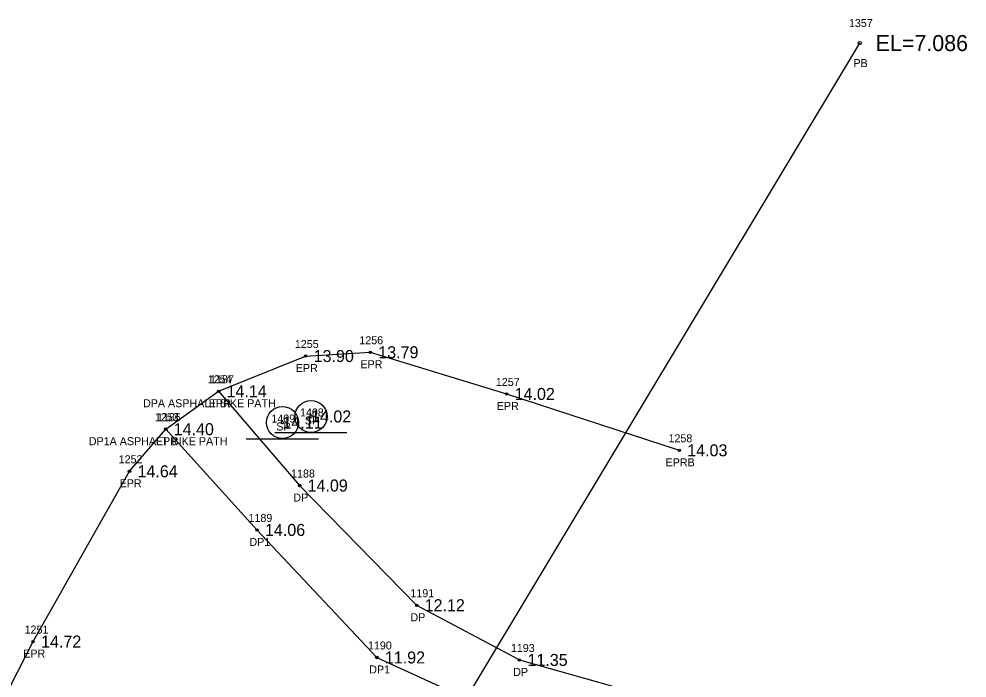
# Model space of a CAD drawing. Extents: x 2072307 to 2072993, y 127574 to 129736.
# Drawn here: x 2072874.9 to 2072993.3, y 128591.5 to 128673.9 of the extents above; entities that cross this region are included whole.
import ezdxf

# ---------------------------------------------------------------- set-up
doc = ezdxf.new("R2010")
doc.units = 0
for name, color, linetype in [('RD_EX_BldgApp', 7, 'Continuous'), ('RD_EX_BldgApp_txCode', 7, 'Continuous'), ('RD_EX_DR_Pipe', 7, 'Continuous'), ('RD_EX_DR_Pipe_txCode', 7, 'Continuous'), ('RD_EX_Driveway', 7, 'Continuous'), ('RD_EX_Driveway_txCode', 7, 'Continuous'), ('RD_EX_Road', 7, 'Continuous'), ('RD_EX_Road_txCode', 7, 'Continuous'), ('RD_EX_TX_BldgApp_ELEV', 7, 'Continuous'), ('RD_EX_TX_Driveway_ELEV', 7, 'Continuous'), ('RD_EX_TX_Road_ELEV', 7, 'Continuous'), ('RD_SMD_Locator', 7, 'Continuous'), ('RD_TX_Pipe_ElevEX', 7, 'Continuous')]:
    doc.layers.add(name, color=color, linetype=linetype)

msp = doc.modelspace()

# ---------------------------------------------------------------- linework, layer by layer
at = {"layer": 'RD_EX_BldgApp'}
for p, q in [((2072906.88, 128622.19), (2072915.88, 128622.19)), ((2072903.31, 128621.42), (2072912.31, 128621.42))]:
    msp.add_line(p, q, dxfattribs=at)
for centre in [(2072907.82, 128623.45), (2072911.39, 128624.21)]:
    msp.add_circle(centre, 2, dxfattribs=at)
at = {"layer": 'RD_EX_DR_Pipe'}
msp.add_line((2072924.18, 128577.97), (2072979.91, 128670.87), dxfattribs=at)
at = {"layer": 'RD_EX_Driveway'}
for points in [[(2072899.84, 128627.36), (2072909.96, 128615.58), (2072924.58, 128600.62), (2072937.42, 128593.78), (2072957.44, 128588.15)], [(2072893.24, 128622.62), (2072904.64, 128610.03), (2072919.61, 128594.09), (2072934.96, 128587.05), (2072955.54, 128580.39)]]:
    msp.add_lwpolyline(points, dxfattribs=at)
at = {"layer": 'RD_EX_Road'}
msp.add_lwpolyline([(2072789.45, 128345.69), (2072789.46, 128382.93), (2072788.01, 128408.09), (2072794.06, 128431.26), (2072804.3, 128453.88), (2072840.7, 128525.64), (2072876.68, 128596.08), (2072888.72, 128617.36), (2072893.24, 128622.62), (2072899.84, 128627.36), (2072910.72, 128631.76), (2072918.79, 128632.23), (2072935.82, 128627.02), (2072957.37, 128619.98)], dxfattribs=at)
at = {"layer": 'RD_SMD_Locator'}
for centre, radius in [((2072979.91, 128670.87), 0.2), ((2072910.72, 128631.76), 0.15), ((2072918.79, 128632.23), 0.15), ((2072899.84, 128627.36), 0.15), ((2072899.84, 128627.36), 0.15), ((2072935.82, 128627.02), 0.15), ((2072911.39, 128624.21), 0.15), ((2072907.82, 128623.45), 0.15), ((2072893.24, 128622.62), 0.15), ((2072893.24, 128622.62), 0.15), ((2072957.37, 128619.98), 0.15), ((2072888.72, 128617.36), 0.15), ((2072909.96, 128615.58), 0.15), ((2072904.64, 128610.03), 0.15), ((2072924.58, 128600.62), 0.15), ((2072876.68, 128596.08), 0.15), ((2072919.61, 128594.09), 0.15), ((2072937.42, 128593.78), 0.15)]:
    msp.add_circle(centre, radius, dxfattribs=at)

# ---------------------------------------------------------------- texts
at = {"layer": 'RD_EX_BldgApp_txCode'}
for s, p in [('1409', (2072906.44, 128623.45)), ('1408', (2072910.01, 128624.21)), ('SP', (2072910.62, 128623.21)), ('SP', (2072907.05, 128622.45))]:
    msp.add_text(s, height=1, dxfattribs=at).set_placement(p)
at = {"layer": 'RD_EX_DR_Pipe_txCode'}
for s, p in [('1357', (2072978.56, 128672.87)), ('PB', (2072979.13, 128667.87))]:
    msp.add_text(s, height=1, dxfattribs=at).set_placement(p)
at = {"layer": 'RD_EX_Driveway_txCode'}
for s, p in [('1187', (2072898.78, 128628.36)), ('DPA ASPHALT BIKE PATH', (2072890.41, 128625.36)), ('1186', (2072892.15, 128623.62)), ('DP1A ASPHALT BIKE PATH', (2072883.64, 128620.62)), ('1188', (2072908.9, 128616.58)), ('DP', (2072909.18, 128613.58)), ('1189', (2072903.58, 128611.03)), ('DP1', (2072903.7, 128608.03)), ('1191', (2072923.8, 128601.62)), ('DP', (2072923.8, 128598.62)), ('1190', (2072918.5, 128595.09)), ('1193', (2072936.35, 128594.78)), ('DP1', (2072918.66, 128592.09)), ('DP', (2072936.64, 128591.78))]:
    msp.add_text(s, height=1, dxfattribs=at).set_placement(p)
at = {"layer": 'RD_EX_Road_txCode'}
for s, p in [('1255', (2072909.37, 128632.76)), ('1256', (2072917.42, 128633.23)), ('EPR', (2072909.49, 128629.76)), ('EPR', (2072917.56, 128630.23)), ('1254', (2072898.5, 128628.36)), ('1257', (2072934.47, 128628.02)), ('EPR', (2072898.61, 128625.36)), ('EPR', (2072934.59, 128625.02)), ('1253', (2072891.89, 128623.62)), ('1258', (2072956.03, 128620.98)), ('EPR', (2072892.01, 128620.62)), ('1252', (2072887.37, 128618.36)), ('EPRB', (2072955.67, 128617.98)), ('EPR', (2072887.49, 128615.36)), ('1251', (2072875.62, 128597.08)), ('EPR', (2072875.45, 128594.08))]:
    msp.add_text(s, height=1, dxfattribs=at).set_placement(p)
at = {"layer": 'RD_EX_TX_BldgApp_ELEV'}
for s, p in [('14.11', (2072907.82, 128622.7)), ('14.02', (2072911.39, 128623.46))]:
    msp.add_text(s, height=1.5, dxfattribs=at).set_placement(p)
at = {"layer": 'RD_EX_TX_Driveway_ELEV'}
for s, p in [('14.14', (2072900.84, 128626.61)), ('14.40', (2072894.24, 128621.87)), ('14.09', (2072910.96, 128614.83)), ('14.06', (2072905.64, 128609.28)), ('12.12', (2072925.58, 128599.87)), ('11.92', (2072920.61, 128593.34)), ('11.35', (2072938.42, 128593.03))]:
    msp.add_text(s, height=1.5, dxfattribs=at).set_placement(p)
at = {"layer": 'RD_EX_TX_Road_ELEV'}
for s, p in [('13.90', (2072911.72, 128631.01)), ('13.79', (2072919.79, 128631.48)), ('14.14', (2072900.84, 128626.61)), ('14.02', (2072936.82, 128626.27)), ('14.40', (2072894.24, 128621.87)), ('14.03', (2072958.37, 128619.23)), ('14.64', (2072889.72, 128616.61)), ('14.72', (2072877.68, 128595.33))]:
    msp.add_text(s, height=1.5, dxfattribs=at).set_placement(p)
at = {"layer": 'RD_TX_Pipe_ElevEX'}
msp.add_text('EL=7.086', height=2, dxfattribs=at).set_placement((2072981.91, 128669.87))

doc.saveas('drawing.dxf')
